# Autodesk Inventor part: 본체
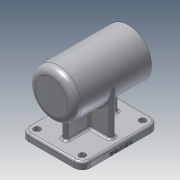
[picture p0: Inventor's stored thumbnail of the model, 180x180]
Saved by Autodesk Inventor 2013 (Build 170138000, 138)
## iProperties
Created: 2020-10
Part Number: 본체
Material: 알루미늄 6061
Document SubType Name: Modeling
Designer: 88
Density: 1 g/cm^3
Author: 88
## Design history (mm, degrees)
sketch "스케치1"
  geometry: C1 r 34 at (0, 0); 1 further point
  constraints: 1 centre point, 1 coincident
  dimensions: "d0" = 68 diameter of C1
extrude "돌출1" new body sketch "스케치1" stored distance "d1" = 112; taper "d2" = 0 deg
sketch "스케치2"
  geometry: L1 (34, -56)-(-34, -56) reference; L2 (-34, -56)-(-34, 56) reference; L3 (-34, 56)-(34, 56) reference; L4 (34, 56)-(34, -56) reference; L5 (0, -56)-(0, 56); L6 (0, -56)-(21, -56); L7 (21, -56)-(21, -41); L8 (21, -41)-(24, -41); L9 (24, -41)-(24, 13); L10 (24, 13)-(21, 13); L11 (21, 13)-(21, 25); L12 (21, 25)-(17.5, 25); L13 (17.5, 25)-(17.5, 43); L14 (17.5, 43)-(16, 43); L15 (16, 43)-(16, 47); L16 (16, 47)-(10.5, 47); L17 (10.5, 47)-(10.5, 50); L18 (10.5, 50)-(0, 50); 1 further point
  constraints: 28 end point, 8 parallel, 4 perpendicular, 2 midpoint, 2 point on line
  dimensions: "d3" = 42 diameter of L7 L5; "d5" = 48 diameter of L9 L5; "d6" = 15 distance of L6.end L7.end; "d7" = 42 diameter of L11 L5; "d8" = 54 distance of L8.end L9.end; "d9" = 12 distance of L10.end L11.end; "d10" = 35 diameter of L13 L5; "d11" = 18 distance of L12.end L13.end; "d12" = 32 diameter of L15 L5; "d13" = 4 distance of L14.end L15.end; "d14" = 21 diameter of L17 L5; "d15" = 3 distance of L16.end L17.end
revolve "회전1" sketch "스케치2" stored, may be unused: angle "d16" = 90 deg
node "작업 평면1"
sketch "스케치3"
  geometry: L1 (45, -56)-(-45, -56); L2 (-45, -56)-(-45, 56); L3 (-45, 56)-(45, 56); L4 (45, 56)-(45, -56); L5 (45, -56)-(-45, 56); L6 (-45, -56)-(45, 56); 1 further point
  constraints: 12 end point, 2 midpoint, 2 parallel, 1 horizontal, 1 perpendicular
  dimensions: "d18" = 90 distance of L2.end L3.end; "d19" = 112 distance of L1.end L2.end
extrude "돌출2" join sketch "스케치3" distance "d20" = 10; taper "d21" = 0 deg
sketch "스케치4"
  geometry: L1 (-4, -38)-(4, -38); L2 (4, -38)-(4, 38); L3 (4, 38)-(-4, 38); L4 (-4, 38)-(-4, -38); L5 (-4, -38)-(4, 38); L6 (4, -38)-(-4, 38); L7 (34, -4)-(-34, -4); L8 (-34, -4)-(-34, 4); L9 (-34, 4)-(34, 4); L10 (34, 4)-(34, -4); L11 (34, -4)-(-34, 4); L12 (-34, -4)-(34, 4); 1 further point
  constraints: 24 end point, 4 midpoint, 4 parallel, 2 horizontal, 2 perpendicular
  dimensions: "d22" = 8 distance of L2.end L3.end; "d24" = 76 distance of L1.end L2.end; "d25" = 68 distance of L8.end L9.end; "d26" = 8 distance of L7.end L8.end
extrude "돌출3" join sketch "스케치4" stored distance "d27" = 0; taper "d28" = 0 deg
sketch "스케치5" dims "d29" = 52
  geometry: C1 r 21 at (0, 0) reference; C2 r 34 at (0, 0) reference; 2 further points
  constraints: 2 vertical alignment, 1 coincident, 2 other
hole "구멍1" sketch "스케치5" at (0, 26) diameter "d30" = 3.242; stored, may be unused: countersink angle "d34" = 90 deg, drill point angle "d36" = 118 deg; dims "d31" = 8, "d32" = 4, "d33" = 2, "d35" = 11
fillet "모깎기1" dims "d40" = 12
sketch "스케치6"
  geometry: A1 r 12 centre (-33, 44) between (-33, 56) and (-45, 44) reference; A2 r 12 centre (-33, -44) between (-45, -44) and (-33, -56) reference; A3 r 12 centre (33, -44) between (33, -56) and (45, -44) reference; A4 r 12 centre (33, 44) between (45, 44) and (33, 56) reference; 5 further points
  constraints: 4 coincident
hole "구멍2" sketch "스케치6" at (-33, 44), (33, 44), (33, -44), (-33, -44) diameter "d41" = 5.5; stored, may be unused: countersink angle "d45" = 90 deg, drill point angle "d47" = 118 deg; dims "d42" = 8, "d43" = 9.5, "d44" = 5.4, "d46" = 11
sketch "스케치7"
  geometry: L1 (88, 0)-(0, 0) reference; L2 (100, 0)-(100, 10) reference; 2 further points
  constraints: 1 other
  dimensions: "d48" = 56 distance from line of L2 point (44, 3); "d49" = 3 distance from line of L1 point (44, 3)
feature "엠보싱1" sketch "스케치7" dims "d16" = 90 deg, "d50" = 0.5, "d51" = 0
fillet "모깎기2" dims "d52" = 3
fillet "모깎기3" dims "d53" = 10
fillet "모깎기4" dims "d54" = 3
fillet "모깎기5" dims "d55" = 3
fillet "모깎기6" dims "d56" = 0.3
fillet "모깎기7" dims "d57" = 3
fillet "모깎기8" dims "d58" = 3
chamfer "모따기1" distance "d59" = 1; stored, may be unused: second distance "d60" = 2, angle "d61" = 45 deg
node "솔리드1"
pattern_circular "원형 패턴1" dims angle "d38" = 360 deg
node "절단 모서리 투영1"
other parameters: "d17" = -74
